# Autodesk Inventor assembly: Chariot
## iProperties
Created: 2002-04
Part Number: Chariot
Document SubType Name: Assemblage
Designer: Flavien MARTY
Control State: 0
Master: False
Checked Out: False
Shininess: 41.0
Length Units: 11269
Angle Units: 11279
Time Units: 11290
Mass Units: 11283
Length Display Precision: 3
Angle Display Precision: 2
Density: 0.0
Volumn: 0.0
Area: 0.0
PropertySet Name: Model Information
Author: Flavien MARTY
